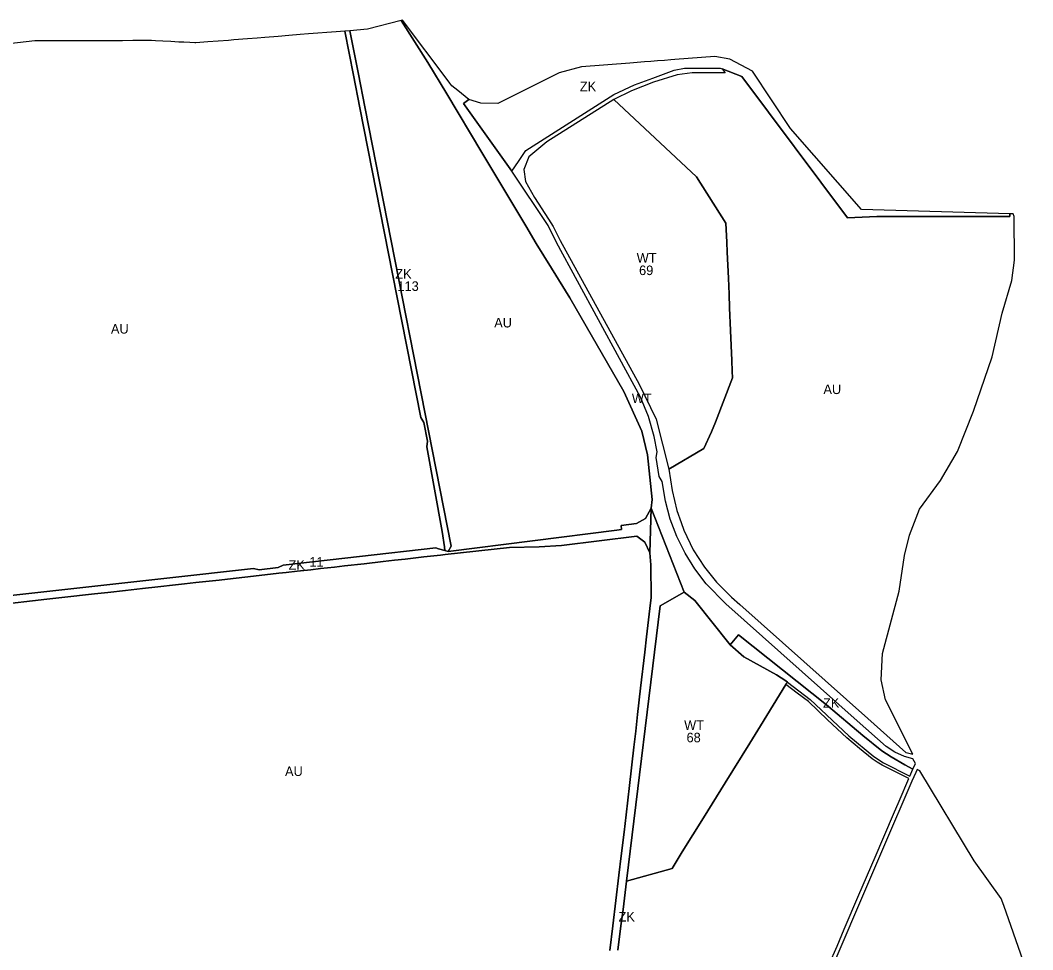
# Model space of a CAD drawing. Extents: x -521939 to -516426, y -1197857 to -1189551.
# Drawn here: x -519323 to -518262, y -1190954 to -1189980 of the extents above; entities that cross this region are included whole.
import ezdxf

# ---------------------------------------------------------------- set-up
doc = ezdxf.new("R2010")
doc.units = 0
for name, color, linetype in [('90640013', 7, 'Continuous'), ('90640023', 7, 'Continuous'), ('90710013', 7, 'Continuous'), ('90710023', 7, 'Continuous'), ('90750013', 7, 'Continuous'), ('ID_navrh', 7, 'Continuous')]:
    doc.layers.add(name, color=color, linetype=linetype)

msp = doc.modelspace()

# ---------------------------------------------------------------- linework, layer by layer
at = {"layer": '90640013'}
msp.add_lwpolyline([(-518923.63, -1189980.1), (-518895.89, -1190023.95), (-518875.89, -1190056.99), (-518839.22, -1190118.41), (-518793.23, -1190195.23), (-518782.38, -1190213.72), (-518766.07, -1190239.39), (-518747.14, -1190270.5), (-518690.5, -1190368.8), (-518671.54, -1190410.25), (-518665.58, -1190435.02), (-518660.73, -1190481.86), (-518661.8, -1190490.82), (-518627.12, -1190579.12), (-518616.2, -1190587.89), (-518579.17, -1190634.29), (-518570.32, -1190623.67), (-518478.1, -1190697.07), (-518440.19, -1190729.11), (-518420.06, -1190745.18), (-518410.33, -1190751.39), (-518396.24, -1190759.86), (-518387.72, -1190764.57), (-518385.06, -1190758.37), (-518387.8, -1190753.49), (-518396.54, -1190751.24), (-518406.57, -1190746.77), (-518415.66, -1190740.62), (-518445.86, -1190713.73), (-518583.63, -1190591.06), (-518604.18, -1190570.24), (-518616, -1190554.71), (-518626.27, -1190538.11), (-518634.89, -1190520.6), (-518641.79, -1190502.34), (-518646.9, -1190483.5), (-518650.35, -1190463.17), (-518653.27, -1190457.92), (-518656.65, -1190438.04), (-518655.63, -1190432.12), (-518658.7, -1190415.83), (-518664.69, -1190394.88), (-518672.95, -1190374.72), (-518760.96, -1190212.6), (-518769.79, -1190194.85), (-518807.85, -1190137.81), (-518858.27, -1190066.88), (-518852.72, -1190062.92), (-518864.3, -1190053.47), (-518870.48, -1190048.43), (-518872.51, -1190045.74), (-518874.49, -1190043.1), (-518922.19, -1189979.73), (-518923.63, -1189980.1)], dxfattribs=at)
at = {"layer": '90640023'}
for points in [[(-518643.4, -1190450.09), (-518606.61, -1190428.32), (-518598.55, -1190411.07), (-518594.44, -1190400.79), (-518576.52, -1190354.3), (-518576.83, -1190347.45), (-518577.28, -1190336.35), (-518578.63, -1190304.8), (-518579.59, -1190281.03), (-518580.25, -1190266.63), (-518580.95, -1190250.13), (-518582.12, -1190222.61), (-518582.56, -1190212.26), (-518583.4, -1190192.5), (-518614.2, -1190143.77), (-518700.81, -1190062.95), (-518770.96, -1190107.15), (-518790.08, -1190122.73), (-518795.26, -1190136.18), (-518793.36, -1190148.8), (-518784.15, -1190165.5), (-518769.16, -1190188.04), (-518764.54, -1190195.99), (-518757.02, -1190210.42), (-518674.29, -1190361.03), (-518656.44, -1190397.83), (-518643.4, -1190450.09)], [(-518627.12, -1190579.12), (-518652.45, -1190593.34), (-518687.6, -1190881.68), (-518639.88, -1190868.49), (-518629.18, -1190851.22), (-518607.03, -1190815.46), (-518584.36, -1190778.86), (-518558.52, -1190737.14), (-518547.39, -1190719.17), (-518520.57, -1190675.85), (-518518.98, -1190673.29), (-518520.61, -1190672.06), (-518530.66, -1190665.45), (-518564.68, -1190646.91), (-518579.17, -1190634.29), (-518616.2, -1190587.89), (-518627.12, -1190579.12)]]:
    msp.add_lwpolyline(points, dxfattribs=at)
at = {"layer": '90710013'}
for points in [[(-518286.14, -1190182.43), (-518441.52, -1190177.94), (-518515.7, -1190093.14), (-518555.8, -1190033.18), (-518579.43, -1190020.59), (-518595.19, -1190017.86), (-518636.93, -1190021), (-518641.1, -1190021.31), (-518647.72, -1190021.81), (-518655.1, -1190022.37), (-518662.16, -1190022.9), (-518668.76, -1190023.4), (-518676.37, -1190023.97), (-518684.3, -1190024.57), (-518734.78, -1190028.38), (-518758.1, -1190034.86), (-518810.55, -1190061.06), (-518822.31, -1190066.94), (-518840.17, -1190066.73), (-518852.72, -1190062.92), (-518858.27, -1190066.88), (-518807.85, -1190137.81), (-518800.92, -1190127.9), (-518793.23, -1190116.22), (-518700.76, -1190057.67), (-518679.13, -1190047.44), (-518659.99, -1190040.35), (-518637.85, -1190032.2), (-518626.95, -1190029.79), (-518589.5, -1190029.9), (-518587.33, -1190030.75), (-518566.71, -1190038.83), (-518456.27, -1190186.72), (-518425.5, -1190185.32), (-518309.38, -1190185.23), (-518286.16, -1190185.34), (-518286.14, -1190182.43)], [(-518627.12, -1190579.12), (-518661.8, -1190490.82), (-518663.34, -1190537.95), (-518662, -1190550.2), (-518661.95, -1190584.47), (-518663.27, -1190596.1), (-518666.64, -1190625.78), (-518668.38, -1190641.83), (-518672.81, -1190679.52), (-518676.02, -1190707.19), (-518677.9, -1190724.82), (-518679.82, -1190741.27), (-518684.48, -1190781.71), (-518688.01, -1190812.2), (-518690.17, -1190830.63), (-518693.13, -1190855.41), (-518695.52, -1190875.6), (-518701.87, -1190928.62), (-518705, -1190954.5)], [(-518696.61, -1190954.07), (-518693.43, -1190928.61), (-518691.21, -1190911.5), (-518687.6, -1190881.68), (-518652.45, -1190593.34), (-518627.12, -1190579.12)], [(-518390.75, -1190771.64), (-518387.72, -1190764.57), (-518396.24, -1190759.86), (-518410.33, -1190751.39), (-518420.06, -1190745.18), (-518440.19, -1190729.11), (-518478.1, -1190697.07), (-518570.32, -1190623.67), (-518579.17, -1190634.29), (-518564.68, -1190646.91), (-518530.66, -1190665.45), (-518520.61, -1190672.06), (-518518.98, -1190673.29), (-518495.13, -1190691.35), (-518454.79, -1190729.54), (-518428.63, -1190751.16), (-518418.46, -1190757.75), (-518390.75, -1190771.64)]]:
    msp.add_lwpolyline(points, dxfattribs=at)
at = {"layer": '90710023'}
for points in [[(-518982.75, -1189991.08), (-518973.66, -1190037.25), (-518966.93, -1190071.42), (-518932.65, -1190245.48), (-518903.01, -1190395.98), (-518899.95, -1190401.14), (-518896.05, -1190420.93), (-518896.92, -1190426.87), (-518880.88, -1190515.41), (-518878.11, -1190531.65), (-518877.94, -1190535.3), (-518874.29, -1190536.33), (-518871.13, -1190530.87), (-518961.73, -1190070.59), (-518968.46, -1190036.36), (-518977.46, -1189990.66), (-518982.75, -1189991.08)], [(-519349.34, -1190592.5), (-519294.71, -1190586.4), (-519279.13, -1190584.54), (-519244.88, -1190580.73), (-519230.8, -1190579.2), (-519212.48, -1190577.18), (-519194.65, -1190575.18), (-519178.48, -1190573.43), (-519159.93, -1190571.22), (-519150.74, -1190570.16), (-519138.65, -1190568.93), (-519128.12, -1190567.71), (-519114.47, -1190566.26), (-519105.69, -1190565.24), (-519096.49, -1190564.2), (-519078.49, -1190562.26), (-519051.92, -1190559.12), (-519044.06, -1190558.34), (-519032.44, -1190556.99), (-519018.45, -1190555.44), (-519008.01, -1190554.21), (-518993.5, -1190552.64), (-518983.05, -1190551.46), (-518962.5, -1190549.15), (-518942.66, -1190546.94), (-518930.55, -1190545.57), (-518919.4, -1190544.34), (-518899.77, -1190542.15), (-518882.35, -1190540.18), (-518877.74, -1190539.66), (-518810.26, -1190532.19), (-518779.08, -1190531.51), (-518755.65, -1190530.1), (-518676.76, -1190520.2), (-518668.57, -1190526.63), (-518663.34, -1190537.95), (-518661.8, -1190490.82), (-518667.64, -1190501.77), (-518677.22, -1190507.17), (-518693.26, -1190509.28), (-518692.74, -1190513.36), (-518697.59, -1190513.92), (-518874.29, -1190536.33), (-518877.94, -1190535.3), (-518884.52, -1190533.45), (-518887.27, -1190532.68), (-519047.1, -1190550.59), (-519052.5, -1190553.21), (-519072.55, -1190555.45), (-519078.39, -1190554.09), (-519168.97, -1190564.24), (-519345.4, -1190584.01)]]:
    msp.add_lwpolyline(points, dxfattribs=at)
at = {"layer": '90750013'}
for points in [[(-518923.63, -1189980.1), (-518958.98, -1189989.18), (-518977.46, -1189990.66), (-518968.46, -1190036.36), (-518961.73, -1190070.59), (-518871.13, -1190530.87), (-518874.29, -1190536.33), (-518697.59, -1190513.92), (-518692.74, -1190513.36), (-518693.26, -1190509.28), (-518677.22, -1190507.17), (-518667.64, -1190501.77), (-518661.8, -1190490.82), (-518660.73, -1190481.86), (-518665.58, -1190435.02), (-518671.54, -1190410.25), (-518690.5, -1190368.8), (-518747.14, -1190270.5), (-518766.07, -1190239.39), (-518782.38, -1190213.72), (-518793.23, -1190195.23), (-518839.22, -1190118.41), (-518875.89, -1190056.99), (-518895.89, -1190023.95), (-518923.63, -1189980.1)], [(-518982.75, -1189991.08), (-518991.78, -1189991.8), (-519020.78, -1189994.11), (-519029.56, -1189994.81), (-519041.28, -1189995.74), (-519052.34, -1189996.62), (-519066.59, -1189997.76), (-519074.47, -1189998.39), (-519084.52, -1189999.2), (-519099.08, -1190000.36), (-519104.6, -1190000.8), (-519126.22, -1190002.51), (-519138.66, -1190003.51), (-519139.71, -1190003.46), (-519144.96, -1190003.18), (-519151.35, -1190002.84), (-519156.46, -1190002.57), (-519165.08, -1190002.12), (-519173.46, -1190001.68), (-519181.03, -1190001.27), (-519185.31, -1190001.05), (-519187.9, -1190001.06), (-519204.78, -1190001.11), (-519215.43, -1190001.14), (-519223.76, -1190001.17), (-519241.98, -1190001.22), (-519263.01, -1190001.29), (-519271.58, -1190001.31), (-519284.59, -1190001.35), (-519297.85, -1190001.39), (-519307.47, -1190001.42), (-519347.33, -1190005.8)], [(-519345.4, -1190584.01), (-519168.97, -1190564.24), (-519078.39, -1190554.09), (-519072.55, -1190555.45), (-519052.5, -1190553.21), (-519047.1, -1190550.59), (-518887.27, -1190532.68), (-518884.52, -1190533.45), (-518877.94, -1190535.3), (-518878.11, -1190531.65), (-518880.88, -1190515.41), (-518896.92, -1190426.87), (-518896.05, -1190420.93), (-518899.95, -1190401.14), (-518903.01, -1190395.98), (-518932.65, -1190245.48), (-518966.93, -1190071.42), (-518973.66, -1190037.25), (-518982.75, -1189991.08)], [(-518286.14, -1190182.43), (-518286.16, -1190185.34), (-518309.38, -1190185.23), (-518425.5, -1190185.32), (-518456.27, -1190186.72), (-518566.71, -1190038.83), (-518587.33, -1190030.75), (-518584.12, -1190034.97), (-518618.94, -1190034.88), (-518624.04, -1190035.52), (-518634.54, -1190036.84), (-518659.18, -1190044.75), (-518682.38, -1190053.63), (-518700.81, -1190062.95), (-518614.2, -1190143.77), (-518583.4, -1190192.5), (-518582.56, -1190212.26), (-518582.12, -1190222.61), (-518580.95, -1190250.13), (-518580.25, -1190266.63), (-518579.59, -1190281.03), (-518578.63, -1190304.8), (-518577.28, -1190336.35), (-518576.83, -1190347.45), (-518576.52, -1190354.3), (-518594.44, -1190400.79), (-518598.55, -1190411.07), (-518606.61, -1190428.32), (-518643.4, -1190450.09), (-518639.66, -1190472.37), (-518634.82, -1190493.56), (-518630.5, -1190505.93), (-518627.66, -1190514.06), (-518617.62, -1190534.74), (-518606.08, -1190552.94), (-518593.43, -1190568.52), (-518577.65, -1190584.34), (-518569.04, -1190592), (-518434.79, -1190711.54), (-518395.09, -1190746.89), (-518393.28, -1190747.38), (-518387.76, -1190748.88), (-518416.37, -1190691.78), (-518420.69, -1190670.97), (-518419.58, -1190643.37), (-518401.98, -1190577.95), (-518396.58, -1190540.6), (-518391.03, -1190519.28), (-518380.57, -1190491.95), (-518358.63, -1190462.17), (-518340.9, -1190431.55), (-518324.06, -1190389.31), (-518304.44, -1190332.58), (-518294.15, -1190286.66), (-518284.14, -1190252.55), (-518281.37, -1190231.25), (-518281.49, -1190185.23), (-518282.66, -1190182.53), (-518286.14, -1190182.43)], [(-518705, -1190954.5), (-518701.87, -1190928.62), (-518695.52, -1190875.6), (-518693.13, -1190855.41), (-518690.17, -1190830.63), (-518688.01, -1190812.2), (-518684.48, -1190781.71), (-518679.82, -1190741.27), (-518677.9, -1190724.82), (-518676.02, -1190707.19), (-518672.81, -1190679.52), (-518668.38, -1190641.83), (-518666.64, -1190625.78), (-518663.27, -1190596.1), (-518661.95, -1190584.47), (-518662, -1190550.2), (-518663.34, -1190537.95), (-518668.57, -1190526.63), (-518676.76, -1190520.2), (-518755.65, -1190530.1), (-518779.08, -1190531.51), (-518810.26, -1190532.19), (-518877.74, -1190539.66), (-518882.35, -1190540.18), (-518899.77, -1190542.15), (-518919.4, -1190544.34), (-518930.55, -1190545.57), (-518942.66, -1190546.94), (-518962.5, -1190549.15), (-518983.05, -1190551.46), (-518993.5, -1190552.64), (-519008.01, -1190554.21), (-519018.45, -1190555.44), (-519032.44, -1190556.99), (-519044.06, -1190558.34), (-519051.92, -1190559.12), (-519078.49, -1190562.26), (-519096.49, -1190564.2), (-519105.69, -1190565.24), (-519114.47, -1190566.26), (-519128.12, -1190567.71), (-519138.65, -1190568.93), (-519150.74, -1190570.16), (-519159.93, -1190571.22), (-519178.48, -1190573.43), (-519194.65, -1190575.18), (-519212.48, -1190577.18), (-519230.8, -1190579.2), (-519244.88, -1190580.73), (-519279.13, -1190584.54), (-519294.71, -1190586.4), (-519349.34, -1190592.5)], [(-518391.94, -1190774.4), (-518405.94, -1190767.38), (-518419.95, -1190760.36), (-518425.18, -1190756.97), (-518430.41, -1190753.58), (-518443.59, -1190742.68), (-518456.78, -1190731.79), (-518476.92, -1190712.71), (-518497.07, -1190693.64), (-518508.82, -1190684.74), (-518520.57, -1190675.85), (-518547.39, -1190719.17), (-518558.52, -1190737.14), (-518584.36, -1190778.86), (-518607.03, -1190815.46), (-518629.18, -1190851.22), (-518639.88, -1190868.49), (-518687.6, -1190881.68), (-518691.21, -1190911.5), (-518693.43, -1190928.61), (-518696.61, -1190954.07)], [(-518262.08, -1190994.23), (-518292.5, -1190907.44), (-518295.13, -1190899.93), (-518323.33, -1190860.64), (-518380.25, -1190766.34), (-518383.03, -1190764.9), (-518384.5, -1190767.87), (-518388.71, -1190777.07), (-518418.31, -1190846.1), (-518488.26, -1191009.23)], [(-518475.51, -1190969.38), (-518467.11, -1190949.79), (-518459.59, -1190932.22), (-518444.15, -1190896.22), (-518427.22, -1190856.72), (-518407.95, -1190811.74), (-518402.05, -1190797.95), (-518391.94, -1190774.4)]]:
    msp.add_lwpolyline(points, dxfattribs=at)

# ---------------------------------------------------------------- texts
at = {"layer": '90640013'}
msp.add_text('WT', height=10, rotation=0, dxfattribs=at).set_placement((-518682.04, -1190380.9))
at = {"layer": '90640023'}
for p in [(-518676.94, -1190233.72), (-518627.24, -1190723.26)]:
    msp.add_text('WT', height=10, rotation=0, dxfattribs=at).set_placement(p)
at = {"layer": '90710013'}
for rotation, p in [(360, (-518736.52, -1190054.12)), (360, (-518481.75, -1190700.08)), (0, (-518695.97, -1190924.1))]:
    msp.add_text('ZK', height=10, rotation=rotation, dxfattribs=at).set_placement(p)
at = {"layer": '90710023'}
for p in [(-518929.81, -1190250.48), (-519041.61, -1190555.56)]:
    msp.add_text('ZK', height=10, rotation=0, dxfattribs=at).set_placement(p)
at = {"layer": '90750013'}
for p in [(-519227.67, -1190308.09), (-518826.18, -1190301.61), (-518481.34, -1190371.41), (-519045.29, -1190771.64)]:
    msp.add_text('AU', height=10, rotation=0, dxfattribs=at).set_placement(p)
at = {"layer": 'ID_navrh'}
for s, rotation, p in [('69', 360, (-518674.43, -1190246.76)), ('113', 360, (-518927.55, -1190263.32)), ('11', 360, (-519019.82, -1190552.27)), ('68', 0, (-518624.73, -1190736.3))]:
    msp.add_text(s, height=10, rotation=rotation, dxfattribs=at).set_placement(p)

doc.saveas('drawing.dxf')
